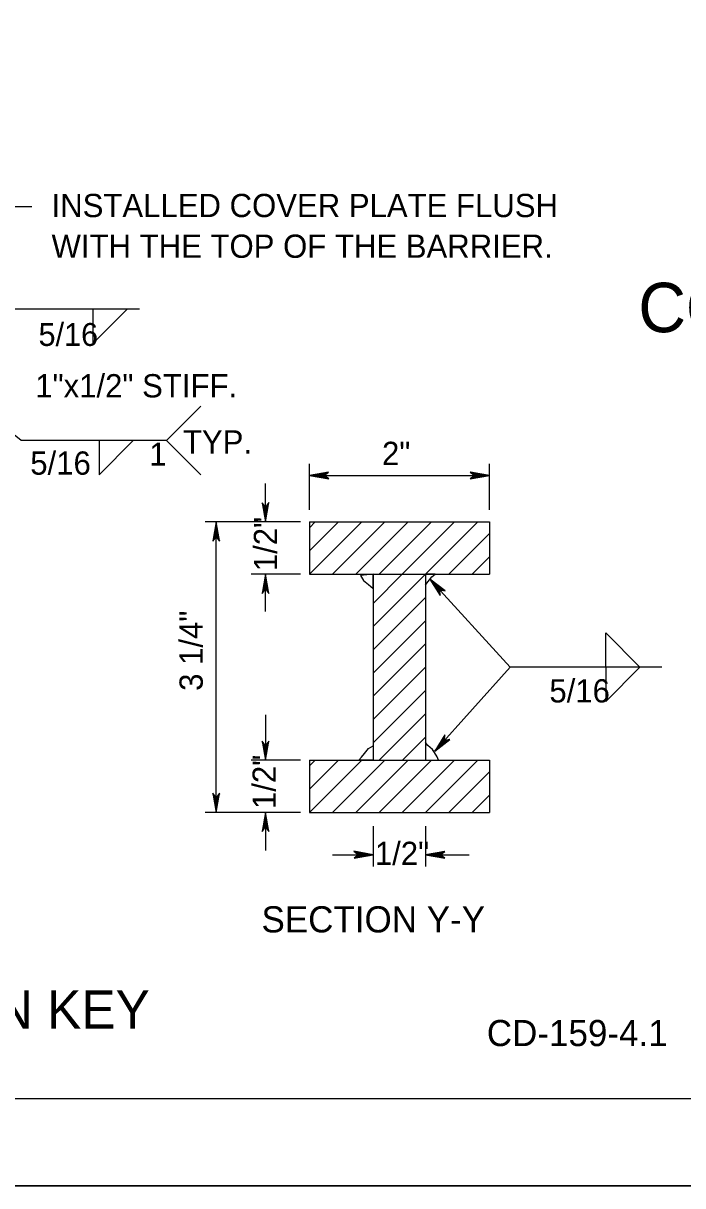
# Model space of a CAD drawing. Extents: x 499866 to 500993, y 499985 to 500645.
# Drawn here: x 500693.7 to 500807.1, y 499985 to 500184.9 of the extents above; entities that cross this region are included whole.
import ezdxf

# ---------------------------------------------------------------- set-up
doc = ezdxf.new("R2010")
doc.units = 0
for name, color, linetype in [('1', 7, 'Continuous'), ('24', 7, 'Continuous'), ('39', 7, 'Continuous'), ('41', 7, 'Continuous'), ('5', 7, 'Continuous'), ('60', 7, 'Continuous')]:
    doc.layers.add(name, color=color, linetype=linetype)

msp = doc.modelspace()

# ---------------------------------------------------------------- linework, layer by layer
at = {"layer": '1'}
for p, q in [((500000, 500000), (500990, 500000)), ((499944.83, 499985), (500993, 499985))]:
    msp.add_line(p, q, dxfattribs=at)
at = {"layer": '24'}
for points in [[(500763.65, 500089.33), (500765.42, 500086.51), (500765.32, 500087.48), (500766.26, 500087.3), (500763.65, 500089.33), (500763.8, 500089.17), (500765.39, 500086.61), (500765.29, 500087.53), (500766.14, 500087.37), (500763.88, 500089.09), (500763.94, 500089), (500765.32, 500086.81), (500765.27, 500087.54), (500766, 500087.41), (500763.98, 500088.96), (500764.06, 500088.89), (500765.26, 500086.98), (500765.25, 500087.56), (500765.85, 500087.5), (500764.28, 500088.66), (500764.4, 500088.52), (500765.21, 500087.16), (500765.22, 500087.58), (500765.68, 500087.55), (500764.41, 500088.49), (500764.52, 500088.35), (500765.16, 500087.35), (500765.18, 500087.67), (500765.51, 500087.64), (500764.64, 500088.24), (500764.74, 500088.1), (500765.11, 500087.49), (500765.15, 500087.69), (500765.4, 500087.66), (500764.8, 500088.05), (500765.03, 500087.64), (500765.08, 500087.77), (500765.31, 500087.71), (500764.89, 500087.98), (500765.04, 500087.7), (500765.03, 500087.86), (500765.17, 500087.8), (500765.01, 500087.84), (500765.04, 500087.77)], [(500735.36, 500058.17), (500735.94, 500061.45), (500735.36, 500060.67), (500734.79, 500061.43), (500735.36, 500058.17), (500735.35, 500058.39), (500735.9, 500061.36), (500735.35, 500060.61), (500734.83, 500061.3), (500735.34, 500058.51), (500735.36, 500058.62), (500735.81, 500061.16), (500735.35, 500060.59), (500734.91, 500061.17), (500735.36, 500058.67), (500735.34, 500058.78), (500735.74, 500061), (500735.36, 500060.57), (500734.96, 500061.01), (500735.34, 500059.09), (500735.34, 500059.28), (500735.66, 500060.83), (500735.37, 500060.53), (500735.04, 500060.86), (500735.36, 500059.31), (500735.37, 500059.49), (500735.57, 500060.65), (500735.34, 500060.43), (500735.12, 500060.67), (500735.36, 500059.65), (500735.38, 500059.81), (500735.51, 500060.51), (500735.35, 500060.4), (500735.18, 500060.59), (500735.36, 500059.9), (500735.47, 500060.35), (500735.34, 500060.29), (500735.22, 500060.49), (500735.34, 500060.01), (500735.42, 500060.31), (500735.32, 500060.19), (500735.26, 500060.33), (500735.35, 500060.19), (500735.37, 500060.26)], [(500764.47, 500059.71), (500767.09, 500061.76), (500766.13, 500061.56), (500766.22, 500062.51), (500764.47, 500059.71), (500764.61, 500059.88), (500766.99, 500061.72), (500766.09, 500061.52), (500766.16, 500062.39), (500764.68, 500059.97), (500764.77, 500060.04), (500766.8, 500061.63), (500766.08, 500061.51), (500766.14, 500062.24), (500764.8, 500060.08), (500764.86, 500060.17), (500766.64, 500061.55), (500766.06, 500061.49), (500766.06, 500062.08), (500765.07, 500060.4), (500765.19, 500060.54), (500766.47, 500061.49), (500766.05, 500061.46), (500766.02, 500061.92), (500765.23, 500060.56), (500765.35, 500060.68), (500766.28, 500061.42), (500765.96, 500061.4), (500765.96, 500061.73), (500765.45, 500060.8), (500765.57, 500060.92), (500766.14, 500061.35), (500765.95, 500061.37), (500765.94, 500061.63), (500765.62, 500060.99), (500766.01, 500061.26), (500765.87, 500061.29), (500765.91, 500061.53), (500765.68, 500061.09), (500765.94, 500061.26), (500765.78, 500061.23), (500765.83, 500061.38), (500765.81, 500061.21), (500765.87, 500061.26)], [(500735.36, 500049.18), (500734.78, 500045.91), (500735.36, 500046.69), (500735.93, 500045.92), (500735.36, 500049.18), (500735.37, 500048.96), (500734.82, 500046), (500735.37, 500046.75), (500735.88, 500046.06), (500735.38, 500048.85), (500735.36, 500048.74), (500734.91, 500046.2), (500735.37, 500046.77), (500735.81, 500046.18), (500735.36, 500048.69), (500735.38, 500048.58), (500734.98, 500046.36), (500735.36, 500046.79), (500735.76, 500046.35), (500735.38, 500048.26), (500735.38, 500048.08), (500735.06, 500046.52), (500735.35, 500046.83), (500735.68, 500046.5), (500735.36, 500048.05), (500735.35, 500047.87), (500735.15, 500046.7), (500735.38, 500046.93), (500735.6, 500046.68), (500735.36, 500047.71), (500735.34, 500047.54), (500735.21, 500046.84), (500735.37, 500046.96), (500735.54, 500046.77), (500735.36, 500047.46), (500735.25, 500047), (500735.38, 500047.07), (500735.5, 500046.87), (500735.38, 500047.34), (500735.3, 500047.04), (500735.4, 500047.17), (500735.46, 500047.03), (500735.37, 500047.17), (500735.35, 500047.09)], [(500735.36, 500049.18), (500734.78, 500045.91), (500735.36, 500046.69), (500735.93, 500045.92), (500735.36, 500049.18), (500735.37, 500048.96), (500734.82, 500046), (500735.37, 500046.75), (500735.88, 500046.06), (500735.38, 500048.85), (500735.36, 500048.74), (500734.91, 500046.2), (500735.37, 500046.77), (500735.81, 500046.18), (500735.36, 500048.69), (500735.38, 500048.58), (500734.98, 500046.36), (500735.36, 500046.79), (500735.76, 500046.35), (500735.38, 500048.26), (500735.38, 500048.08), (500735.06, 500046.52), (500735.35, 500046.83), (500735.68, 500046.5), (500735.36, 500048.05), (500735.35, 500047.87), (500735.15, 500046.7), (500735.38, 500046.93), (500735.6, 500046.68), (500735.36, 500047.71), (500735.34, 500047.54), (500735.21, 500046.84), (500735.37, 500046.96), (500735.54, 500046.77), (500735.36, 500047.46), (500735.25, 500047), (500735.38, 500047.07), (500735.5, 500046.87), (500735.38, 500047.34), (500735.3, 500047.04), (500735.4, 500047.17), (500735.46, 500047.03), (500735.37, 500047.17), (500735.35, 500047.09)]]:
    msp.add_lwpolyline(points, dxfattribs=at)
at = {"layer": '41'}
msp.add_lwpolyline([(499944.83, 500645), (500993, 500645), (500993, 499985), (499944.83, 499985)], close=True, dxfattribs=at)
at = {"layer": '5'}
for p, q in [((500713.68, 500135.74), (500692.28, 500135.74)), ((500711.57, 500135.74), (500705.68, 500129.85)), ((500705.68, 500135.74), (500705.68, 500129.85)), ((500724.24, 500119.03), (500718.35, 500113.14)), ((500712.63, 500113.14), (500706.74, 500107.25)), ((500706.74, 500113.14), (500706.74, 500107.25)), ((500718.35, 500113.14), (500724.24, 500107.25)), ((500742.91, 500101.22), (500742.91, 500109.14)), ((500773.88, 500101.22), (500773.88, 500109.14)), ((500735.36, 500099.14), (500735.36, 500105.75)), ((500742.91, 500107.14), (500773.88, 500107.14)), ((500741.36, 500099.14), (500724.97, 500099.14)), ((500726.89, 500049.18), (500726.89, 500099.14)), ((500742.91, 500099.14), (500742.91, 500090.15)), ((500742.91, 500090.15), (500751.9, 500099.14)), ((500742.91, 500094.15), (500747.9, 500099.14)), ((500742.91, 500098.14), (500743.9, 500099.14)), ((500742.91, 500099.14), (500773.88, 500099.14)), ((500746.9, 500090.15), (500755.9, 500099.14)), ((500750.9, 500090.15), (500759.89, 500099.14)), ((500754.9, 500090.15), (500763.89, 500099.14)), ((500758.89, 500090.15), (500767.89, 500099.14)), ((500762.89, 500090.15), (500771.88, 500099.14)), ((500773.88, 500099.14), (500773.88, 500090.15)), ((500766.89, 500090.15), (500773.88, 500097.15)), ((500770.88, 500090.15), (500773.88, 500093.15)), ((500741.36, 500090.15), (500732.91, 500090.15)), ((500735.36, 500083.76), (500735.36, 500090.15)), ((500742.91, 500090.15), (500773.88, 500090.15)), ((500753.9, 500081.16), (500762.89, 500090.15)), ((500753.9, 500090.15), (500753.9, 500058.17)), ((500753.91, 500085.16), (500758.89, 500090.15)), ((500762.89, 500090.15), (500762.89, 500058.17)), ((500777.43, 500074.16), (500763.65, 500089.33)), ((500753.9, 500077.16), (500762.89, 500086.15)), ((500753.9, 500073.16), (500762.89, 500082.16)), ((500799.76, 500074.16), (500793.87, 500080.05)), ((500793.87, 500074.16), (500793.87, 500080.05)), ((500753.9, 500069.17), (500762.89, 500078.16)), ((500753.9, 500065.17), (500762.89, 500074.16)), ((500777.43, 500074.16), (500764.47, 500059.71)), ((500803.5, 500074.16), (500777.43, 500074.16)), ((500799.76, 500074.16), (500793.87, 500068.27)), ((500793.87, 500074.16), (500793.87, 500068.27)), ((500753.9, 500061.17), (500762.89, 500070.17)), ((500735.36, 500065.97), (500735.36, 500058.17)), ((500754.87, 500058.15), (500762.89, 500066.17)), ((500758.85, 500058.14), (500762.86, 500062.14)), ((500741.36, 500058.17), (500732.91, 500058.17)), ((500742.91, 500058.17), (500742.91, 500049.18)), ((500742.91, 500049.18), (500751.9, 500058.17)), ((500742.91, 500053.18), (500747.9, 500058.17)), ((500742.91, 500057.18), (500743.9, 500058.17)), ((500742.91, 500058.17), (500773.88, 500058.17)), ((500746.9, 500049.18), (500755.9, 500058.17)), ((500750.9, 500049.18), (500759.89, 500058.17)), ((500754.9, 500049.18), (500763.89, 500058.17)), ((500758.89, 500049.18), (500767.89, 500058.17)), ((500762.89, 500049.18), (500771.88, 500058.17)), ((500773.88, 500058.17), (500773.88, 500049.18)), ((500766.89, 500049.18), (500773.88, 500056.18)), ((500770.88, 500049.18), (500773.88, 500052.18)), ((500741.36, 500049.18), (500724.97, 500049.18)), ((500735.36, 500049.18), (500735.36, 500042.65)), ((500742.91, 500049.18), (500773.88, 500049.18)), ((500753.9, 500046.85), (500753.9, 500039.92)), ((500762.89, 500046.85), (500762.89, 500039.92)), ((500746.91, 500041.92), (500753.9, 500041.92)), ((500762.89, 500041.92), (500770.36, 500041.92))]:
    msp.add_line(p, q, dxfattribs=at)
for points in [[(500695.16, 500153.32), (500690.16, 500153.32), (500684.43, 500149.44)], [(500718.35, 500113.14), (500693.34, 500113.14), (500674.91, 500127.92)], [(500742.91, 500107.14), (500746.23, 500106.55), (500745.44, 500107.14), (500746.21, 500107.72), (500742.91, 500107.14), (500743.13, 500107.14), (500746.14, 500106.59), (500745.37, 500107.14), (500746.08, 500107.67), (500743.25, 500107.15), (500743.36, 500107.14), (500745.93, 500106.68), (500745.36, 500107.14), (500745.95, 500107.6), (500743.41, 500107.14), (500743.52, 500107.15), (500745.77, 500106.75), (500745.33, 500107.14), (500745.78, 500107.54), (500743.84, 500107.15), (500744.03, 500107.15), (500745.6, 500106.83), (500745.3, 500107.13), (500745.63, 500107.46), (500744.06, 500107.14), (500744.24, 500107.13), (500745.42, 500106.92), (500745.19, 500107.15), (500745.44, 500107.38), (500744.4, 500107.14), (500744.57, 500107.12), (500745.28, 500106.98), (500745.16, 500107.14), (500745.36, 500107.32), (500744.65, 500107.14), (500745.12, 500107.03), (500745.05, 500107.15), (500745.26, 500107.28), (500744.77, 500107.15), (500745.08, 500107.08), (500744.95, 500107.18), (500745.09, 500107.24), (500744.95, 500107.14), (500745.02, 500107.13)], [(500773.88, 500107.14), (500770.56, 500107.73), (500771.35, 500107.14), (500770.57, 500106.56), (500773.88, 500107.14), (500773.66, 500107.13), (500770.65, 500107.68), (500771.41, 500107.13), (500770.71, 500106.6), (500773.54, 500107.12), (500773.43, 500107.14), (500770.85, 500107.6), (500771.43, 500107.13), (500770.84, 500106.68), (500773.38, 500107.14), (500773.27, 500107.12), (500771.02, 500107.53), (500771.45, 500107.14), (500771.01, 500106.73), (500772.95, 500107.12), (500772.76, 500107.12), (500771.18, 500107.44), (500771.49, 500107.15), (500771.16, 500106.82), (500772.73, 500107.14), (500772.55, 500107.15), (500771.36, 500107.35), (500771.59, 500107.12), (500771.35, 500106.89), (500772.39, 500107.14), (500772.22, 500107.15), (500771.51, 500107.29), (500771.62, 500107.13), (500771.43, 500106.95), (500772.13, 500107.14), (500771.67, 500107.25), (500771.74, 500107.12), (500771.53, 500106.99), (500772.02, 500107.12), (500771.71, 500107.2), (500771.84, 500107.1), (500771.69, 500107.04), (500771.84, 500107.13), (500771.76, 500107.15)], [(500735.36, 500099.14), (500735.95, 500102.47), (500735.36, 500101.67), (500734.78, 500102.45), (500735.36, 500099.14), (500735.35, 500099.36), (500735.9, 500102.37), (500735.35, 500101.61), (500734.83, 500102.32), (500735.34, 500099.48), (500735.36, 500099.59), (500735.82, 500102.17), (500735.35, 500101.59), (500734.9, 500102.19), (500735.36, 500099.65), (500735.34, 500099.76), (500735.75, 500102.01), (500735.36, 500101.57), (500734.95, 500102.02), (500735.34, 500100.08), (500735.34, 500100.26), (500735.67, 500101.84), (500735.37, 500101.54), (500735.04, 500101.87), (500735.36, 500100.3), (500735.37, 500100.48), (500735.57, 500101.66), (500735.34, 500101.43), (500735.12, 500101.68), (500735.36, 500100.64), (500735.38, 500100.81), (500735.51, 500101.52), (500735.35, 500101.4), (500735.17, 500101.59), (500735.36, 500100.89), (500735.47, 500101.36), (500735.34, 500101.29), (500735.22, 500101.49), (500735.34, 500101.01), (500735.42, 500101.31), (500735.32, 500101.19), (500735.26, 500101.33), (500735.35, 500101.19), (500735.37, 500101.26)], [(500726.89, 500099.14), (500726.31, 500095.82), (500726.89, 500096.61), (500727.47, 500095.84), (500726.89, 500099.14), (500726.9, 500098.92), (500726.35, 500095.91), (500726.9, 500096.68), (500727.43, 500095.97), (500726.91, 500098.8), (500726.89, 500098.69), (500726.44, 500096.11), (500726.9, 500096.69), (500727.35, 500096.1), (500726.89, 500098.64), (500726.91, 500098.53), (500726.5, 500096.28), (500726.89, 500096.72), (500727.3, 500096.27), (500726.91, 500098.21), (500726.91, 500098.02), (500726.59, 500096.45), (500726.88, 500096.75), (500727.21, 500096.42), (500726.89, 500097.99), (500726.88, 500097.81), (500726.68, 500096.63), (500726.91, 500096.85), (500727.14, 500096.61), (500726.89, 500097.65), (500726.88, 500097.48), (500726.74, 500096.77), (500726.9, 500096.89), (500727.08, 500096.69), (500726.89, 500097.4), (500726.78, 500096.93), (500726.91, 500097), (500727.04, 500096.79), (500726.91, 500097.28), (500726.83, 500096.97), (500726.93, 500097.1), (500726.99, 500096.95), (500726.9, 500097.1), (500726.88, 500097.02)], [(500735.36, 500090.15), (500734.77, 500086.83), (500735.36, 500087.62), (500735.94, 500086.84), (500735.36, 500090.15), (500735.37, 500089.93), (500734.82, 500086.92), (500735.37, 500087.68), (500735.89, 500086.98), (500735.38, 500089.81), (500735.36, 500089.7), (500734.9, 500087.12), (500735.37, 500087.7), (500735.82, 500087.1), (500735.36, 500089.65), (500735.38, 500089.54), (500734.97, 500087.28), (500735.36, 500087.72), (500735.77, 500087.28), (500735.38, 500089.22), (500735.38, 500089.03), (500735.05, 500087.45), (500735.35, 500087.76), (500735.68, 500087.43), (500735.36, 500089), (500735.35, 500088.82), (500735.15, 500087.63), (500735.38, 500087.86), (500735.6, 500087.61), (500735.36, 500088.66), (500735.34, 500088.49), (500735.21, 500087.78), (500735.37, 500087.89), (500735.54, 500087.7), (500735.36, 500088.4), (500735.25, 500087.94), (500735.38, 500088), (500735.5, 500087.8), (500735.38, 500088.29), (500735.3, 500087.98), (500735.4, 500088.11), (500735.46, 500087.96), (500735.37, 500088.11), (500735.35, 500088.03)], [(500726.89, 500049.18), (500727.48, 500052.51), (500726.89, 500051.71), (500726.31, 500052.49), (500726.89, 500049.18), (500726.89, 500049.4), (500727.44, 500052.41), (500726.89, 500051.65), (500726.36, 500052.35), (500726.88, 500049.52), (500726.89, 500049.63), (500727.35, 500052.21), (500726.89, 500051.63), (500726.44, 500052.23), (500726.89, 500049.68), (500726.88, 500049.79), (500727.28, 500052.05), (500726.89, 500051.61), (500726.49, 500052.06), (500726.88, 500050.11), (500726.88, 500050.3), (500727.2, 500051.88), (500726.9, 500051.57), (500726.57, 500051.9), (500726.89, 500050.34), (500726.9, 500050.51), (500727.11, 500051.7), (500726.88, 500051.47), (500726.65, 500051.72), (500726.89, 500050.68), (500726.91, 500050.84), (500727.05, 500051.56), (500726.89, 500051.44), (500726.71, 500051.63), (500726.89, 500050.93), (500727, 500051.39), (500726.88, 500051.33), (500726.75, 500051.53), (500726.88, 500051.05), (500726.95, 500051.35), (500726.85, 500051.22), (500726.79, 500051.37), (500726.89, 500051.23), (500726.9, 500051.3)], [(500753.9, 500041.92), (500750.57, 500042.51), (500751.37, 500041.92), (500750.59, 500041.34), (500753.9, 500041.92), (500753.68, 500041.91), (500750.67, 500042.46), (500751.43, 500041.91), (500750.72, 500041.38), (500753.56, 500041.9), (500753.45, 500041.92), (500750.87, 500042.38), (500751.45, 500041.91), (500750.85, 500041.46), (500753.4, 500041.92), (500753.29, 500041.9), (500751.03, 500042.31), (500751.47, 500041.92), (500751.02, 500041.51), (500752.96, 500041.9), (500752.78, 500041.9), (500751.2, 500042.22), (500751.51, 500041.93), (500751.17, 500041.6), (500752.74, 500041.92), (500752.57, 500041.93), (500751.38, 500042.13), (500751.61, 500041.9), (500751.36, 500041.67), (500752.4, 500041.92), (500752.24, 500041.93), (500751.52, 500042.07), (500751.64, 500041.91), (500751.45, 500041.73), (500752.15, 500041.92), (500751.68, 500042.03), (500751.75, 500041.9), (500751.55, 500041.77), (500752.03, 500041.9), (500751.73, 500041.98), (500751.85, 500041.88), (500751.71, 500041.82), (500751.85, 500041.91), (500751.78, 500041.93)], [(500762.89, 500041.92), (500766.21, 500041.33), (500765.42, 500041.92), (500766.2, 500042.5), (500762.89, 500041.92), (500763.11, 500041.92), (500766.12, 500041.37), (500765.36, 500041.92), (500766.06, 500042.45), (500763.23, 500041.93), (500763.34, 500041.92), (500765.92, 500041.46), (500765.34, 500041.92), (500765.94, 500042.38), (500763.39, 500041.92), (500763.5, 500041.93), (500765.76, 500041.53), (500765.32, 500041.92), (500765.76, 500042.32), (500763.82, 500041.93), (500764.01, 500041.93), (500765.59, 500041.61), (500765.28, 500041.91), (500765.61, 500042.24), (500764.04, 500041.92), (500764.22, 500041.91), (500765.41, 500041.7), (500765.18, 500041.93), (500765.43, 500042.16), (500764.38, 500041.92), (500764.55, 500041.9), (500765.26, 500041.76), (500765.15, 500041.92), (500765.34, 500042.1), (500764.64, 500041.92), (500765.1, 500041.81), (500765.04, 500041.93), (500765.24, 500042.06), (500764.76, 500041.93), (500765.06, 500041.86), (500764.93, 500041.96), (500765.08, 500042.02), (500764.93, 500041.92), (500765.01, 500041.91)]]:
    msp.add_lwpolyline(points, dxfattribs=at)
at = {"layer": '60'}
for points in [[(500753.9, 500090.15), (500751.7, 500089.96), (500752.23, 500089.08), (500753.1, 500088.38), (500753.89, 500087.68)], [(500762.89, 500090.15), (500762.89, 500088.29), (500763.11, 500088.64), (500763.55, 500089.17), (500763.99, 500089.7), (500764.52, 500090.15)], [(500753.9, 500058.17), (500752.23, 500058.17), (500751.43, 500058.17), (500751.87, 500058.7), (500752.4, 500059.31), (500753.1, 500060.19), (500753.9, 500060.63)], [(500762.89, 500058.17), (500765.13, 500058.17), (500764.87, 500058.78), (500764.43, 500059.49), (500764.08, 500060.01), (500763.29, 500060.72), (500762.89, 500061.24)]]:
    msp.add_lwpolyline(points, close=True, dxfattribs=at)

# ---------------------------------------------------------------- texts
at = {"layer": '39'}
msp.add_text('CD-159-4.1', height=4.5, dxfattribs=at).set_placement((500773.42, 500009.01))
at = {"layer": '5'}
for s, height, p in [('INSTALLED COVER PLATE FLUSH ', 4, (500698.57, 500151.56)), ('WITH THE TOP OF THE BARRIER.', 4, (500698.57, 500144.56)), ('CONSTRUCTION BARRIER CURB', 8.5, (500799.47, 500131.77)), ('5/16', 3.937, (500696.33, 500129.41)), ('1"x1/2" STIFF.', 4, (500695.77, 500120.56)), ('TYP.', 4, (500721.16, 500110.91)), ('5/16', 4, (500694.91, 500107.27)), ('1', 3.94, (500715.4, 500108.84)), ('2"', 4, (500755.4, 500108.93)), ('5/16', 4, (500784.18, 500068.1)), ('1/2"', 4, (500754.17, 500040.15)), ('SECTION Y-Y', 4.5, (500734.67, 500028.56)), ('CONNECTION KEY', 6.6001, (500636.02, 500012.01))]:
    msp.add_text(s, height=height, dxfattribs=at).set_placement(p)
for s, p in [('1/2"', (500737.36, 500090.68)), ('3 1/4"', (500724.57, 500070.1)), ('1/2"', (500737.13, 500049.78))]:
    msp.add_text(s, height=4, rotation=90, dxfattribs=at).set_placement(p)

doc.saveas('drawing.dxf')
